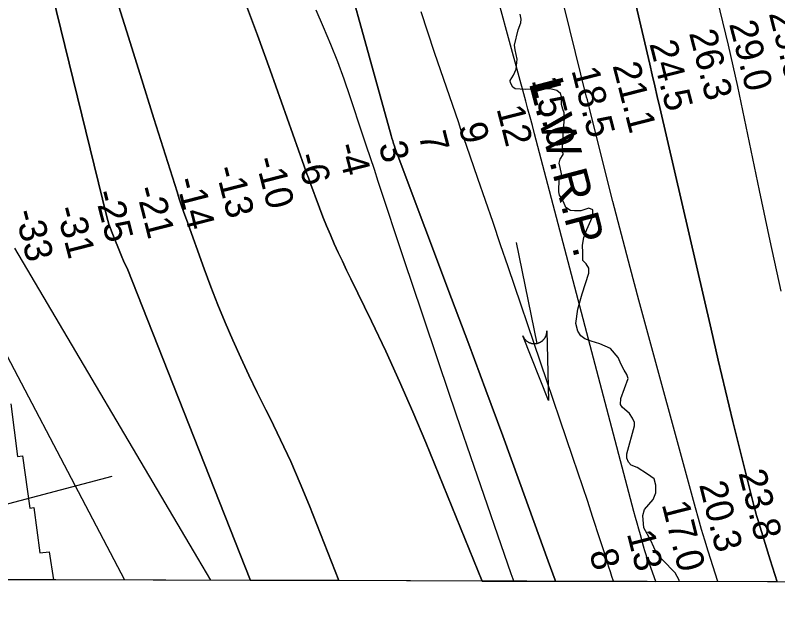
# Model space of a CAD drawing. Extents: x 3161665 to 3199565, y 885729 to 911164.
# Drawn here: x 3177817 to 3179674, y 891109 to 892537 of the extents above; entities that cross this region are included whole.
import ezdxf

# ---------------------------------------------------------------- set-up
doc = ezdxf.new("R2010")
doc.units = 0
for name, color, linetype in [('V-GRID-FRAM', 7, 'Continuous'), ('V-RIVR-EDGE', 7, 'Continuous'), ('V-RIVR-RANG', 7, 'Continuous'), ('V-RRAP-RVMT', 7, 'Continuous'), ('V-STRM-FLOW', 7, 'Continuous'), ('V-TOPO-DPTH', 7, 'Continuous'), ('V-TOPO-MAJR', 7, 'Continuous'), ('V-TOPO-MINR', 7, 'Continuous'), ('V-TOPO-WATR', 7, 'Continuous'), ('V-TOPO-WATR-IDEN', 7, 'Continuous')]:
    doc.layers.add(name, color=color, linetype=linetype)

msp = doc.modelspace()

# ---------------------------------------------------------------- linework, layer by layer
at = {"layer": 'V-GRID-FRAM'}
msp.add_lwpolyline([(3165935.6, 909383.8), (3197271.3, 909297.2), (3197229, 891108.8), (3165877.4, 891195.5), (3165935.6, 909383.8)], dxfattribs=at)
at = {"layer": 'V-RIVR-EDGE'}
for points in [[(3179142.5, 892098.9), (3179141.2, 892107.2), (3179142.2, 892138.9), (3179147, 892145), (3179147.4, 892150.6), (3179144.4, 892166.3), (3179142.3, 892176.7), (3179144.5, 892186.7), (3179151.5, 892198), (3179149.8, 892213.2), (3179152.5, 892261), (3179155.2, 892284.9), (3179154.3, 892299.3), (3179150.9, 892308.4), (3179147.4, 892319.7), (3179147.5, 892338.8), (3179144.9, 892346.7), (3179136.6, 892354.1), (3179119.7, 892358), (3179095.3, 892356.8), (3179059.3, 892356), (3179034.5, 892357.8), (3179029.3, 892362.2), (3179023.2, 892372.6), (3179022.8, 892378.3), (3179030.7, 892390.9), (3179037.2, 892406.1), (3179039.9, 892430.4), (3179034.7, 892452.6), (3179033.5, 892463.9), (3179042.2, 892501.7), (3179048.8, 892519), (3179049.7, 892527.7), (3179046.7, 892539.5)], [(3179434, 891158), (3179434, 891161), (3179425, 891178.9), (3179393.7, 891210.7), (3179379.9, 891225.9), (3179365.2, 891258.1), (3179348.3, 891289), (3179346.2, 891319), (3179349.7, 891333.8), (3179371.1, 891357.7), (3179377.2, 891374.2), (3179377.7, 891392.4), (3179373.4, 891408.5), (3179356.9, 891419.8), (3179331.7, 891435.6), (3179317.8, 891441.2), (3179310.9, 891449.1), (3179307, 891458.2), (3179306.6, 891468.7), (3179325.4, 891537.3), (3179325.5, 891545.5), (3179320.7, 891556), (3179313.3, 891566.9), (3179295.6, 891583), (3179291.7, 891589.5), (3179292.1, 891603.9), (3179310.1, 891652.5), (3179306.6, 891662.1), (3179300.1, 891672.5), (3179293.2, 891686.9), (3179285.4, 891703.4), (3179266.8, 891725.7), (3179241.2, 891737), (3179219.9, 891743.2), (3179204.7, 891749.3), (3179195.1, 891756.7), (3179187.3, 891767.6), (3179183, 891786.3), (3179187.5, 891821), (3179198.4, 891858.8), (3179214.6, 891909.2), (3179214.7, 891921), (3179208.2, 891931.4), (3179199.9, 891940.1), (3179199.6, 891958.8), (3179199.2, 891977.1), (3179202.3, 891995.7), (3179209.3, 892015.3), (3179222.8, 892044.8), (3179224.1, 892055.7), (3179224.2, 892063.5), (3179214.2, 892067), (3179194.6, 892060.5), (3179179.4, 892060.6), (3179169.4, 892061.9), (3179158.5, 892068.9), (3179152.5, 892082.8), (3179147.3, 892093.2), (3179142.5, 892098.9)]]:
    msp.add_lwpolyline(points, dxfattribs=at)
at = {"layer": 'V-RIVR-RANG'}
msp.add_line((3177240.6, 891201.4), (3178053.1, 891414.3), dxfattribs=at)
at = {"layer": 'V-RRAP-RVMT'}
for p, q in [((3177806.4, 891590.7), (3177822.4, 891462.7)), ((3177822.4, 891462.7), (3177834.5, 891464.3)), ((3177834.5, 891464.3), (3177852.5, 891336.4)), ((3177852.5, 891336.4), (3177862.2, 891338.3)), ((3177862.2, 891338.3), (3177877.1, 891228)), ((3177877.1, 891228), (3177899.8, 891230.6)), ((3177899.8, 891230.6), (3177910.1, 891162.2)), ((3177910.1, 891162.2), (3177567, 891163.2))]:
    msp.add_line(p, q, dxfattribs=at)
at = {"layer": 'V-STRM-FLOW'}
msp.add_line((3179037.6, 891983.3), (3179087.7, 891738), dxfattribs=at)
msp.add_lwpolyline([(3179112.1, 891768.5), (3179116.1, 891599.3), (3179053.3, 891756.5), (3179054.6, 891753.7), (3179056.1, 891751.2), (3179056.8, 891750.2), (3179057.4, 891749.4), (3179058.2, 891748.4), (3179059, 891747.4), (3179059.7, 891746.7), (3179060.7, 891745.7), (3179061.9, 891744.6), (3179062.6, 891744.1), (3179063.4, 891743.4), (3179064.6, 891742.5), (3179065.6, 891741.9), (3179066.7, 891741.3), (3179067.4, 891740.9), (3179068.2, 891740.5), (3179069.2, 891740), (3179070.1, 891739.6), (3179071, 891739.3), (3179071.8, 891739), (3179073, 891738.6), (3179074.1, 891738.3), (3179075, 891738.1), (3179076.1, 891737.9), (3179077, 891737.7), (3179077.9, 891737.6), (3179078.5, 891737.5), (3179079.5, 891737.4), (3179080.5, 891737.4), (3179081.5, 891737.4), (3179082.5, 891737.4), (3179083.4, 891737.4), (3179084.4, 891737.5), (3179085.3, 891737.6), (3179086.4, 891737.8), (3179087.7, 891738), (3179088.2, 891738.1), (3179088.8, 891738.2), (3179089.5, 891738.4), (3179090.1, 891738.6), (3179090.8, 891738.8), (3179091.4, 891739), (3179092.2, 891739.3), (3179092.7, 891739.5), (3179093.5, 891739.8), (3179094.2, 891740.1), (3179094.6, 891740.3), (3179095.8, 891740.9), (3179096.5, 891741.2), (3179096.9, 891741.5), (3179097.6, 891741.9), (3179098.2, 891742.3), (3179098.8, 891742.7), (3179099.6, 891743.2), (3179100.3, 891743.7), (3179100.8, 891744.1), (3179101.2, 891744.5), (3179101.8, 891745), (3179102.3, 891745.4), (3179102.9, 891746), (3179103.4, 891746.5), (3179104, 891747.1), (3179104.7, 891747.9), (3179105.2, 891748.5), (3179105.7, 891749.1), (3179106.2, 891749.8), (3179106.5, 891750.3), (3179106.9, 891750.9), (3179107.5, 891751.7), (3179107.5, 891751.8), (3179107.9, 891752.3), (3179108.1, 891752.7), (3179108.4, 891753.3), (3179108.8, 891754.1), (3179109.1, 891754.7), (3179109.4, 891755.2), (3179109.7, 891755.9), (3179110, 891756.7), (3179110.2, 891757.2), (3179110.4, 891757.8), (3179110.7, 891758.7), (3179110.9, 891759.3), (3179111, 891759.7), (3179111.1, 891760.1), (3179111.3, 891760.6), (3179111.4, 891761.3), (3179111.5, 891761.9), (3179111.7, 891762.5), (3179111.8, 891763.2), (3179111.9, 891764), (3179111.9, 891764.5), (3179112, 891765.3), (3179112.1, 891766.2), (3179112.1, 891766.9), (3179112.1, 891767.4), (3179112.1, 891767.9), (3179112.1, 891768.2)], close=True, dxfattribs=at)
at = {"layer": 'V-TOPO-DPTH'}
for points in [[(3179220.3, 893027.4), (3179362.5, 892417.9), (3179368.7, 892391.6), (3179374.8, 892365.4), (3179380.9, 892339.1), (3179387, 892312.7), (3179511.9, 891772.4), (3179529.4, 891697.5), (3179547.2, 891622.8), (3179565.4, 891548.1), (3179583.9, 891473.5), (3179617.4, 891340), (3179619.4, 891332.2), (3179621.5, 891324.4), (3179623.7, 891316.6), (3179626, 891308.9), (3179656.2, 891210.8), (3179673.4, 891157.4), (3179377.2, 891158.2)], [(3178605.4, 891160.3), (3178390.2, 891160.9), (3178089.4, 891920.8), (3178084.7, 891929.9), (3178080.5, 891939.1), (3178076.5, 891948.5), (3178051.4, 892011.3), (3178048.2, 892019.8), (3178045.3, 892028.4), (3178042.7, 892037.1), (3178040.3, 892045.9), (3177897.3, 892629.6), (3177883.1, 892687.4), (3177868.9, 892745.3), (3177854.7, 892803.1), (3177840.4, 892860.9), (3177813.2, 892971.3)], [(3177813.2, 892971.3), (3177840.4, 892860.9), (3177854.7, 892803.1), (3177868.9, 892745.3), (3177883.1, 892687.4), (3177897.3, 892629.6), (3178040.3, 892045.9), (3178042.7, 892037.1), (3178045.3, 892028.4), (3178048.2, 892019.8), (3178051.4, 892011.3), (3178076.5, 891948.5), (3178080.5, 891939.1), (3178084.7, 891929.9), (3178089.4, 891920.8), (3178390.2, 891160.9)], [(3179132.8, 891158.8), (3179131.9, 891161.4), (3179126.3, 891176.8), (3179120.7, 891192.1), (3179115.1, 891207.5), (3179045.2, 891400.7), (3179004.4, 891512.6), (3178963.3, 891624.3), (3178921.8, 891735.9), (3178880, 891847.4), (3178749.7, 892193.2), (3178747.3, 892199.5), (3178745, 892205.8), (3178742.8, 892212.2), (3178740.7, 892218.6), (3178738.7, 892225.1), (3178736.7, 892231.5), (3178734.8, 892238), (3178732.9, 892244.5), (3178567.9, 892839.2)], [(3178567.9, 892839.2), (3178732.9, 892244.5), (3178734.8, 892238), (3178736.7, 892231.5), (3178738.7, 892225.1), (3178740.7, 892218.6), (3178742.8, 892212.2), (3178745, 892205.8), (3178747.3, 892199.5), (3178749.7, 892193.2), (3178880, 891847.4), (3178921.8, 891735.9), (3178963.3, 891624.3), (3179004.4, 891512.6), (3179045.2, 891400.7), (3179115.1, 891207.5), (3179120.7, 891192.1), (3179126.3, 891176.8), (3179131.9, 891161.4), (3179132.8, 891158.8), (3179377.2, 891158.2)], [(3178605.4, 891160.3), (3178533.6, 891342.8), (3178511.4, 891396.8), (3178488.3, 891450.4), (3178463.6, 891503.3), (3178438, 891555.7), (3178427.6, 891576.3), (3178406.7, 891618.3), (3178386.3, 891660.5), (3178366.5, 891703), (3178347.1, 891745.7), (3178328.5, 891788.7), (3178310.5, 891832), (3178293.5, 891875.7), (3178277.1, 891919.7), (3178233.9, 892039.9), (3178228, 892056.5), (3178222.3, 892073.2), (3178216.7, 892090), (3178211.2, 892106.8), (3178154.5, 892285.9), (3178121, 892392.4), (3178087.7, 892498.9), (3178054.9, 892605.6)], [(3178054.9, 892605.6), (3178087.7, 892498.9), (3178121, 892392.4), (3178154.5, 892285.9), (3178211.2, 892106.8), (3178216.7, 892090), (3178222.3, 892073.2), (3178228, 892056.5), (3178233.9, 892039.9), (3178277.1, 891919.7), (3178293.5, 891875.7), (3178310.5, 891832), (3178328.5, 891788.7), (3178347.1, 891745.7), (3178366.5, 891703), (3178386.3, 891660.5), (3178406.7, 891618.3), (3178427.6, 891576.3), (3178438, 891555.7), (3178463.6, 891503.3), (3178488.3, 891450.4), (3178511.4, 891396.8), (3178533.6, 891342.8), (3178605.4, 891160.3)], [(3178375.6, 892573.2), (3178407.5, 892488.5), (3178438.3, 892403.3), (3178520.9, 892169.5), (3178524.3, 892160), (3178527.7, 892150.6), (3178531.1, 892141.2), (3178534.6, 892131.8), (3178558.1, 892068.4), (3178566.6, 892046.3), (3178575.4, 892024.3), (3178584.6, 892002.5), (3178594.1, 891980.8), (3178604, 891959.3), (3178614, 891937.9), (3178624.2, 891916.5), (3178634.4, 891895.2), (3178684.7, 891792.1), (3178719.5, 891718.9), (3178753.3, 891645.3), (3178785.6, 891571.1), (3178817, 891496.4), (3178954.6, 891159.3), (3179132.8, 891158.8)], [(3178375.6, 892573.2), (3178407.5, 892488.5), (3178438.3, 892403.3), (3178520.9, 892169.5), (3178524.3, 892160), (3178527.7, 892150.6), (3178531.1, 892141.2), (3178534.6, 892131.8), (3178558.1, 892068.4), (3178566.6, 892046.3), (3178575.4, 892024.3), (3178584.6, 892002.5), (3178594.1, 891980.8), (3178604, 891959.3), (3178614, 891937.9), (3178624.2, 891916.5), (3178634.4, 891895.2), (3178684.7, 891792.1), (3178719.5, 891718.9), (3178753.3, 891645.3), (3178785.6, 891571.1), (3178817, 891496.4), (3178954.6, 891159.3), (3178605.4, 891160.3)], [(3179377.2, 891158.2), (3179357.7, 891212.7), (3179355.9, 891217.7), (3179354.2, 891222.7), (3179352.5, 891227.7), (3179350.9, 891232.7), (3179348.2, 891241.3), (3179348, 891242), (3179347.3, 891244.3), (3179339.8, 891271.4), (3179335.9, 891285.6), (3179332, 891299.9), (3179328.1, 891314.3), (3179324.3, 891328.6), (3179082, 892248.7), (3179076.7, 892268.6), (3179071.4, 892288.5), (3179066.1, 892308.3), (3179060.7, 892328.1), (3179021.1, 892473.3), (3178995.6, 892565.7)], [(3179377.2, 891158.2), (3179357.7, 891212.7), (3179355.9, 891217.7), (3179354.2, 891222.7), (3179352.5, 891227.7), (3179350.9, 891232.7), (3179348.2, 891241.3), (3179348, 891242), (3179347.3, 891244.3), (3179339.8, 891271.4), (3179335.9, 891285.6), (3179332, 891299.9), (3179328.1, 891314.3), (3179324.3, 891328.6), (3179082, 892248.7), (3179076.7, 892268.6), (3179071.4, 892288.5), (3179066.1, 892308.3), (3179060.7, 892328.1), (3179021.1, 892473.3), (3178995.6, 892565.7)], [(3178390.2, 891160.9), (3177677.8, 891162.9)]]:
    msp.add_lwpolyline(points, dxfattribs=at)
at = {"layer": 'V-TOPO-MAJR'}
msp.add_lwpolyline([(3177814.9, 891970.2), (3178261, 891214.6), (3178293, 891161.2)], dxfattribs=at)
at = {"layer": 'V-TOPO-MINR'}
for points in [[(3179683.2, 891865.5), (3179656.1, 891988), (3179629.8, 892110.6), (3179577, 892363.4), (3179571.6, 892388.6), (3179566, 892413.8), (3179560.2, 892439), (3179554.3, 892464.2), (3179444.9, 892916.3), (3179430, 892977.5), (3179415.1, 893038.6), (3179400, 893099.6), (3179384.8, 893160.7), (3179359.7, 893261.5), (3179357.2, 893272.2), (3179354.8, 893282.8), (3179352.7, 893293.5), (3179350.7, 893304.3), (3179337.9, 893379.8), (3179329.8, 893428.3), (3179321.8, 893476.8), (3179313.9, 893525.4), (3179306.3, 893574), (3179246.9, 893954.3)], [(3179673.4, 891157.4), (3179656.2, 891210.8), (3179626, 891308.9), (3179623.7, 891316.6), (3179621.5, 891324.4), (3179619.4, 891332.2), (3179617.4, 891340), (3179583.9, 891473.5), (3179565.4, 891548.1), (3179547.2, 891622.8), (3179529.4, 891697.5), (3179511.9, 891772.4), (3179387, 892312.7), (3179380.9, 892339.1), (3179374.8, 892365.4), (3179368.7, 892391.6), (3179362.5, 892417.9), (3179220.3, 893027.4)], [(3177813.2, 892971.3), (3177840.4, 892860.9), (3177854.7, 892803.1), (3177868.9, 892745.3), (3177883.1, 892687.4), (3177897.3, 892629.6), (3178040.3, 892045.9), (3178042.7, 892037.1), (3178045.3, 892028.4), (3178048.2, 892019.8), (3178051.4, 892011.3), (3178076.5, 891948.5), (3178080.5, 891939.1), (3178084.7, 891929.9), (3178089.4, 891920.8), (3178390.2, 891160.9)], [(3179132.8, 891158.8), (3179131.9, 891161.4), (3179126.3, 891176.8), (3179120.7, 891192.1), (3179115.1, 891207.5), (3179045.2, 891400.7), (3179004.4, 891512.6), (3178963.3, 891624.3), (3178921.8, 891735.9), (3178880, 891847.4), (3178749.7, 892193.2), (3178747.3, 892199.5), (3178745, 892205.8), (3178742.8, 892212.2), (3178740.7, 892218.6), (3178738.7, 892225.1), (3178736.7, 892231.5), (3178734.8, 892238), (3178732.9, 892244.5), (3178567.9, 892839.2)], [(3179528.4, 891157.8), (3179504.9, 891232.4), (3179496.8, 891258.6), (3179488.9, 891284.9), (3179481.4, 891311.2), (3179474, 891337.6), (3179336.5, 891843.1), (3179315, 891923.1), (3179293.8, 892003.1), (3179273.1, 892083.3), (3179252.7, 892163.5), (3179215.6, 892310.9), (3179214, 892317.6), (3179212.3, 892324.2), (3179210.7, 892330.8), (3179209, 892337.4), (3179127.3, 892667.7)], [(3178054.9, 892605.6), (3178087.7, 892498.9), (3178121, 892392.4), (3178154.5, 892285.9), (3178211.2, 892106.8), (3178216.7, 892090), (3178222.3, 892073.2), (3178228, 892056.5), (3178233.9, 892039.9), (3178277.1, 891919.7), (3178293.5, 891875.7), (3178310.5, 891832), (3178328.5, 891788.7), (3178347.1, 891745.7), (3178366.5, 891703), (3178386.3, 891660.5), (3178406.7, 891618.3), (3178427.6, 891576.3), (3178438, 891555.7), (3178463.6, 891503.3), (3178488.3, 891450.4), (3178511.4, 891396.8), (3178533.6, 891342.8), (3178605.4, 891160.3)], [(3178954.6, 891159.3), (3178817, 891496.4), (3178785.6, 891571.1), (3178753.3, 891645.3), (3178719.5, 891718.9), (3178684.7, 891792.1), (3178634.4, 891895.2), (3178624.2, 891916.5), (3178614, 891937.9), (3178604, 891959.3), (3178594.1, 891980.8), (3178584.6, 892002.5), (3178575.4, 892024.3), (3178566.6, 892046.3), (3178558.1, 892068.4), (3178534.6, 892131.8), (3178531.1, 892141.2), (3178527.7, 892150.6), (3178524.3, 892160), (3178520.9, 892169.5), (3178438.3, 892403.3), (3178407.5, 892488.5), (3178375.6, 892573.2)], [(3179031.4, 891159.1), (3179029.9, 891163.5), (3179025.3, 891176.8), (3178935, 891438.5), (3178892.1, 891563.5), (3178849.6, 891688.5), (3178807.4, 891813.7), (3178765.6, 891939), (3178701.3, 892132.4), (3178691.8, 892161.1), (3178682.3, 892189.8), (3178672.7, 892218.5), (3178663.2, 892247.2), (3178633, 892338.2), (3178618.1, 892381.1), (3178602.5, 892423.7), (3178585.7, 892465.8), (3178568.1, 892507.7), (3178549.7, 892549.2)], [(3179274.3, 891158.5), (3179274.1, 891159.1), (3179270.4, 891170.3), (3179266.8, 891181.6), (3179263.2, 891192.9), (3179260.8, 891200.8), (3179258.5, 891208.2), (3179256.2, 891215.5), (3179253.9, 891222.8), (3179251.7, 891230.2), (3179249.4, 891237.5), (3179247.1, 891244.8), (3179244.7, 891252.1), (3179242.3, 891259.4), (3179223.6, 891316.7), (3179211.8, 891352.6), (3179199.9, 891388.5), (3179187.8, 891424.3), (3179175.7, 891460.2), (3179017.7, 891924.2), (3178999.3, 891978.1), (3178980.9, 892032), (3178962.4, 892085.9), (3178943.8, 892139.7), (3178916, 892220.2), (3178911.3, 892233.8), (3178906.6, 892247.5), (3178901.9, 892261.1), (3178897.3, 892274.8), (3178838.7, 892446.1), (3178805.6, 892545.6)], [(3177469.4, 892518.9), (3177478.6, 892514.5), (3177487.5, 892505.1), (3177624.3, 892108), (3177632.1, 892085), (3177639.7, 892062), (3177647.1, 892038.9), (3177654.3, 892015.8), (3177663.7, 891985.2), (3177666.2, 891977.3), (3177668.6, 891969.4), (3177671, 891961.5), (3177673.4, 891953.7), (3177675.9, 891945.8), (3177678.4, 891937.9), (3177681, 891930.1), (3177683.6, 891922.3), (3178082.8, 891161.8)]]:
    msp.add_lwpolyline(points, dxfattribs=at)
at = {"layer": 'V-TOPO-WATR'}
msp.add_lwpolyline([(3179377.2, 891158.2), (3179357.7, 891212.7), (3179355.9, 891217.7), (3179354.2, 891222.7), (3179352.5, 891227.7), (3179350.9, 891232.7), (3179348.2, 891241.3), (3179348, 891242), (3179347.3, 891244.3), (3179339.8, 891271.4), (3179335.9, 891285.6), (3179332, 891299.9), (3179328.1, 891314.3), (3179324.3, 891328.6), (3179082, 892248.7), (3179076.7, 892268.6), (3179071.4, 892288.5), (3179066.1, 892308.3), (3179060.7, 892328.1), (3179021.1, 892473.3), (3178995.6, 892565.7)], dxfattribs=at)

# ---------------------------------------------------------------- texts
at = {"layer": 'V-RIVR-RANG'}
for s, rotation, p in [('29.5', 284.3656, (3179652.3, 892541.5)), ('29.0', 284.3656, (3179555.6, 892516.1)), ('26.3', 284.3656, (3179458, 892493.9)), ('24.5', 284.3656, (3179361.5, 892467.8)), ('21.1', 284.3656, (3179271.8, 892414.8)), ('18.5', 284.3656, (3179171.6, 892403.3)), ('15.0', 284.3656, (3179074.6, 892379)), ('12', 284.3656, (3178989.1, 892309.7)), ('9', 284.3656, (3178896.7, 892267.5)), ('7', 284.3656, (3178799, 892245.7)), ('-4', 284.3656, (3178599.3, 892219.3)), ('3', 284.3656, (3178701.9, 892221.6)), ('-10', 284.3656, (3178401.4, 892186)), ('-6', 284.3656, (3178502.3, 892195)), ('-13', 284.3656, (3178303.9, 892163.7)), ('-14', 284.3656, (3178207.8, 892135.8)), ('-25', 284.3656, (3178009.3, 892104.8)), ('-21', 284.3656, (3178110.1, 892114.3)), ('-31', 284.3656, (3177916.1, 892065.7)), ('-33', 284.3656, (3177814.9, 892057.7)), ('23.8', 284.2928, (3179578.3, 891422.7)), ('20.3', 284.2928, (3179482.5, 891394.1)), ('17.0', 284.2928, (3179391.5, 891346.3)), ('13', 284.2928, (3179306.6, 891275.1)), ('8', 284.2928, (3179215.2, 891229.1))]:
    msp.add_text(s, height=67, rotation=rotation, dxfattribs=at).set_placement(p)
at = {"layer": 'V-TOPO-WATR-IDEN'}
msp.add_text('L.W.R.P.', height=83, rotation=284.7531, dxfattribs=at).set_placement((3179067.6, 892372.6))

doc.saveas('drawing.dxf')
